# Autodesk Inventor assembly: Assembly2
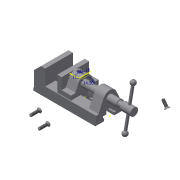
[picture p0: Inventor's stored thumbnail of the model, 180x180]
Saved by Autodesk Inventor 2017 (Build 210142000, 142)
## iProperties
Created: 2016-04
Part Number: Assembly2
Document SubType Name: Assembly
Designer: Sandeep
Author: Sandeep
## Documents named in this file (11)
- C:\Users\Sandeep\Desktop\New folder\joint tut\Assembly2.iam
- C:\Users\Sandeep\Desktop\New folder\joint tut\Base1.ipt
- C:\Users\Sandeep\Desktop\New folder\joint tut\base plate.ipt
- C:\Users\Sandeep\Desktop\New folder\joint tut\vice jaw.ipt
- C:\Users\Sandeep\Desktop\New folder\joint tut\jaw screw.ipt
- C:\Users\Sandeep\Desktop\New folder\joint tut\clamping plate.ipt
- C:\Users\Sandeep\Desktop\New folder\joint tut\Oval Filister.ipt
- C:\Users\Sandeep\Desktop\New folder\joint tut\Screw Bar.ipt
- C:\Users\Sandeep\Desktop\New folder\joint tut\bar globes.ipt
- C:\Users\Sandeep\Desktop\New folder\joint tut\set scew 1.ipt
- C:\Users\Sandeep\Desktop\New folder\joint tut\set scew 2.ipt
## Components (14 placed, 10 different names)
1. Base1:1 — Cylindrical:8, Insert:3, Insert:4, Insert:5, Insert:6, Slider:1
2. base plate:1 — Insert:5, Insert:6
3. base plate:2 — Insert:3, Insert:4, Mate:9, Mate:10
4. vice jaw:1 — Slider:1, Mate:7, Insert:7, Mate:8, Rigid:4
5. jaw screw:1 — Cylindrical:8, Mate:7, Cylindrical:9
6. clamping plate:1 — Insert:7, Mate:8
7. Oval Filister:1 — Rigid:4
8. Screw Bar:1 — Cylindrical:9, Rigid:2, Rigid:3
9. bar globes:1 — Rigid:2
10. bar globes:2 — Rigid:3
11. set scew 1:1
12. set scew 1:2 — Mate:9, Mate:10
13. set scew 2:1
14. set scew 2:2
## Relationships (15: Insert 5, Mate 4, WeldJoint 3, CylindricalJoint 2, TranslationJoint 1)
- Cylindrical:8: Base1:1 ↔ jaw screw:1
- Insert:3: Base1:1 ↔ base plate:2
- Insert:4: Base1:1 ↔ base plate:2
- Insert:5: Base1:1 ↔ base plate:1
- Insert:6: Base1:1 ↔ base plate:1
- Slider:1 [TranslationJoint]: Base1:1 ↔ vice jaw:1
- Mate:7: vice jaw:1 ↔ jaw screw:1
- Cylindrical:9: jaw screw:1 ↔ Screw Bar:1
- Rigid:2 [WeldJoint]: Screw Bar:1 ↔ bar globes:1
- Rigid:3 [WeldJoint]: Screw Bar:1 ↔ bar globes:2
- Insert:7: vice jaw:1 ↔ clamping plate:1
- Mate:8: vice jaw:1 ↔ clamping plate:1
- Rigid:4 [WeldJoint]: vice jaw:1 ↔ Oval Filister:1
- Mate:9: base plate:2 ↔ set scew 1:2
- Mate:10: base plate:2 ↔ set scew 1:2
